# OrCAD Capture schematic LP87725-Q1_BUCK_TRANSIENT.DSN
size A; title: LP87725-Q1 Transient PSpice testbench; rev: 0.9
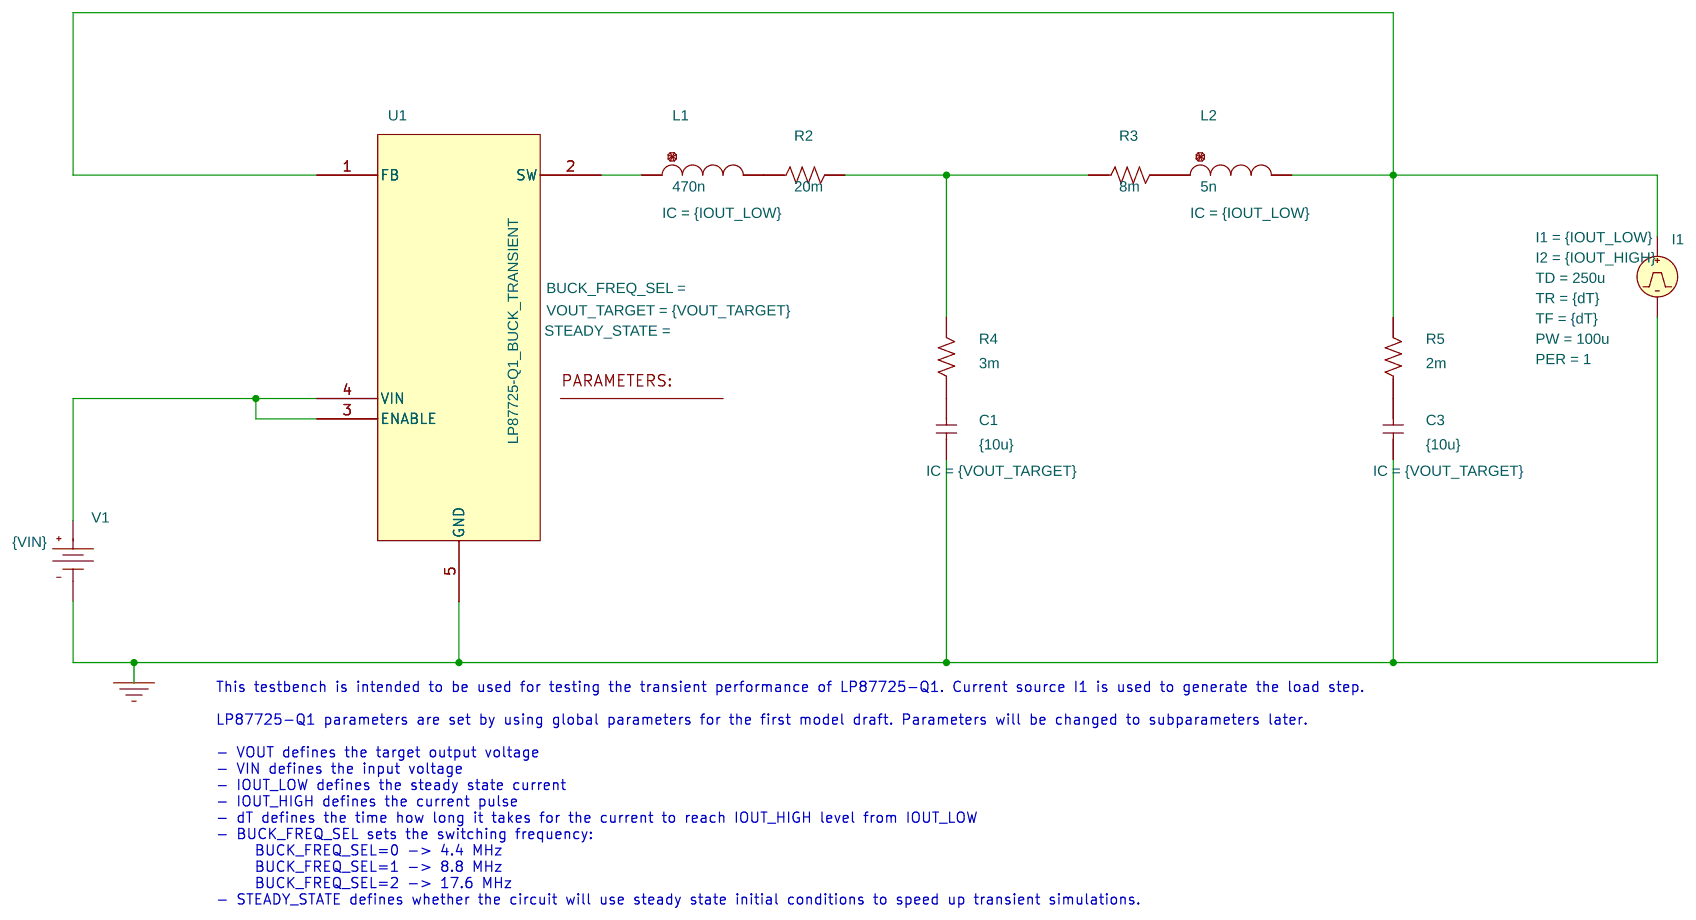
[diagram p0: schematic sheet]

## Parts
1  PARAM
C1  {10u}  [cap196]
C3  {10u}  [cap196]
I1  IPULSE
L1  470n  [DISC350x175LS200x100034]
L2  5n  [DISC350x175LS200x100034]
R2  20m  [AXRC05]
R3  8m  [AXRC05]
R4  3m  [AXRC05]
R5  2m  [AXRC05]
U1  LP87725-Q1_BUCK_TRANSIENT
V1  VDC

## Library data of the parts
1 = PARAM: IOUT_HIGH: 2; VIN: 3.3; VOUT_TARGET: 1.8; dT: 1u
C1 C3 = C: IC: {VOUT_TARGET}
I1 = IPULSE: I1: {IOUT_LOW}; I2: {IOUT_HIGH}; PER: 1; PW: 100u; TD: 250u; TF: {dT}; TR: {dT}
L1 L2 = L: IC: {IOUT_LOW}
R2-R5 = R
U1 = LP87725-Q1_BUCK_TRANSIENT: VOUT_TARGET: {VOUT_TARGET}
V1 = VDC: DC: {VIN}

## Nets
0: C1.2 C3.2 I1.2(-) U1.5(GND) V1.1(-)
N03485: I1.1(+) L2.2 R5.2 U1.1(FB)
N11884: R2.2 R3.1 R4.2
N12034: L1.1 U1.2(SW)
N13795: U1.3(ENABLE) U1.4(VIN) V1.0(+)
N19231: C1.1 R4.1
N19233: L2.1 R3.2
N19234: C3.1 R5.1
N19245: L1.2 R2.1

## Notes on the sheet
- This testbench is intended to be used for testing the transient performance of LP87725-Q1. Current source I1 is used to generate the load step.
  LP87725-Q1 parameters are set by using global parameters for the first model draft. Parameters will be changed to subparameters later.
  - VOUT defines the target output voltage
  - VIN defines the input voltage
  - IOUT_LOW defines the steady state current
  - IOUT_HIGH defines the current pulse
  - dT defines the time how long it takes for the current to reach IOUT_HIGH level from IOUT_LOW
  - BUCK_FREQ_SEL sets the switching frequency:
       BUCK_FREQ_SEL=0 -> 4.4 MHz
       BUCK_FREQ_SEL=1 -> 8.8 MHz
       BUCK_FREQ_SEL=2 -> 17.6 MHz
  - STEADY_STATE defines whether the circuit will use steady state initial conditions to speed up transient simulations.
